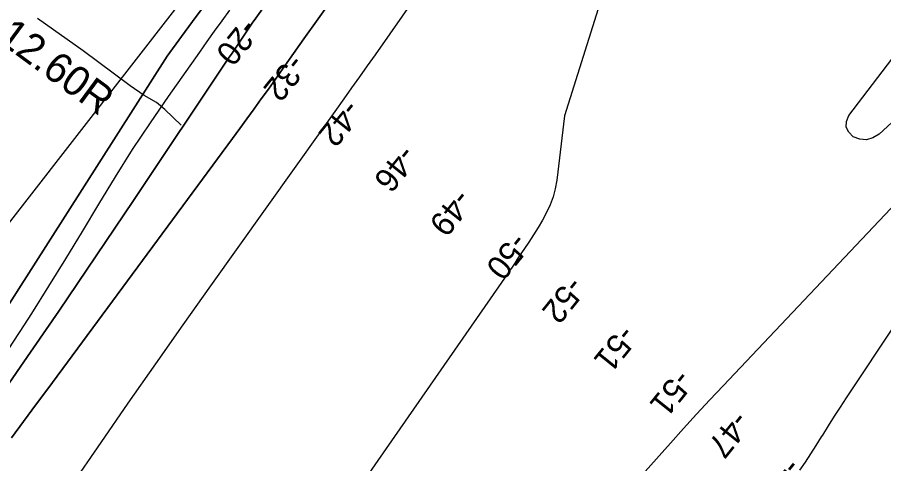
# Model space of a CAD drawing. Extents: x 3896831 to 3918110, y 171006 to 193349.
# Drawn here: x 3911133 to 3912353, y 185832 to 186461 of the extents above; entities that cross this region are included whole.
import ezdxf

# ---------------------------------------------------------------- set-up
doc = ezdxf.new("R2010")
doc.units = 0
for name, color, linetype in [('V-LEVE-TOET', 7, 'Continuous'), ('V-RIVR-RANG', 7, 'Continuous'), ('V-STRM-FMON', 7, 'Continuous'), ('V-TOPO-DPTH', 7, 'Continuous'), ('V-TOPO-MAJR', 7, 'Continuous'), ('V-TOPO-MINR', 7, 'Continuous')]:
    doc.layers.add(name, color=color, linetype=linetype)

msp = doc.modelspace()

# ---------------------------------------------------------------- linework, layer by layer
at = {"layer": 'V-LEVE-TOET'}
msp.add_lwpolyline([(3911363.8, 186309.1), (3911340.8, 186331.3), (3911329.3, 186341.2), (3911311.9, 186350.8), (3911292, 186364.5), (3911225.8, 186413.7), (3911161.8, 186459.6)], dxfattribs=at)
at = {"layer": 'V-TOPO-DPTH'}
for points in [[(3910975.3, 185824.5), (3910982.9, 185836.6), (3910990.4, 185848.6), (3910997.8, 185860.8), (3911005, 185873.1), (3911012, 185885.5), (3911344.1, 186406.2), (3911364.5, 186434.2), (3911384.9, 186462.3), (3911405.5, 186490.2), (3911426.2, 186518), (3911451, 186551), (3911484.1, 186595.3), (3911517.2, 186639.6), (3911550.2, 186683.9), (3911583.3, 186728.3), (3911836.5, 187068.6), (3911837.2, 187069.6), (3911839.4, 187072.5), (3911840.9, 187074.5), (3911842.4, 187076.4), (3912183.1, 187527.7)], [(3912020.4, 186958.3), (3911636.9, 186408.5), (3911626, 186392.9), (3911615, 186377.3), (3911604, 186361.8), (3911592.9, 186346.3), (3911580.3, 186328.6), (3911575.5, 186322), (3911570.8, 186315.3), (3911566, 186308.7), (3911561.3, 186302), (3911405.3, 186082.9), (3911366.4, 186027.9), (3911327.6, 185972.7), (3911289, 185917.3), (3911250.7, 185861.8), (3911208.3, 185800.1)], [(3912020.4, 186958.3), (3911636.9, 186408.5), (3911626, 186392.9), (3911615, 186377.3), (3911604, 186361.8), (3911592.9, 186346.3), (3911580.3, 186328.6), (3911575.5, 186322), (3911570.8, 186315.3), (3911566, 186308.7), (3911561.3, 186302), (3911405.3, 186082.9), (3911366.4, 186027.9), (3911327.6, 185972.7), (3911289, 185917.3), (3911250.7, 185861.8), (3911208.3, 185800.1)], [(3912235, 185822.9), (3912242.9, 185834.5), (3912250.7, 185846.2), (3912258.2, 185858), (3912265.7, 185869.9), (3912267.3, 185872.5), (3912275.5, 185885.7), (3912283.9, 185898.9), (3912292.3, 185911.9), (3912300.9, 185924.9), (3912442.8, 186138), (3912480.3, 186193), (3912518.5, 186247.6), (3912557.7, 186301.3), (3912597.7, 186354.6), (3912639.3, 186408.9), (3912659, 186434.6), (3912678.7, 186460.4), (3912698.3, 186486.2), (3912717.9, 186512), (3912941.8, 186807.2), (3912984.3, 186863.8), (3913012.1, 186901.3)], [(3912235, 185822.9), (3912242.9, 185834.5), (3912250.7, 185846.2), (3912258.2, 185858), (3912265.7, 185869.9), (3912267.3, 185872.5), (3912275.5, 185885.7), (3912283.9, 185898.9), (3912292.3, 185911.9), (3912300.9, 185924.9), (3912442.8, 186138), (3912480.3, 186193), (3912518.5, 186247.6), (3912557.7, 186301.3), (3912597.7, 186354.6), (3912639.3, 186408.9), (3912659, 186434.6), (3912678.7, 186460.4), (3912698.3, 186486.2), (3912717.9, 186512), (3912941.8, 186807.2), (3912984.3, 186863.8), (3913012.1, 186901.3)], [(3911757.1, 186865.4), (3911469, 186459.8), (3911464.1, 186452.8), (3911459.3, 186445.9), (3911454.5, 186438.9), (3911449.7, 186431.9), (3911445, 186424.8), (3911440.3, 186417.8), (3911435.5, 186410.8), (3911430.8, 186403.7), (3911296.8, 186203.2), (3911244.3, 186125.1), (3911191.5, 186047.2), (3911138.2, 185969.5), (3911084.7, 185892.1)], [(3911084.7, 185892.1), (3911138.2, 185969.5), (3911191.5, 186047.2), (3911244.3, 186125.1), (3911296.8, 186203.2), (3911430.8, 186403.7), (3911435.5, 186410.8), (3911440.3, 186417.8), (3911445, 186424.8), (3911449.7, 186431.9), (3911454.5, 186438.9), (3911459.3, 186445.9), (3911464.1, 186452.8), (3911469, 186459.8), (3911757.1, 186865.4)], [(3911577.1, 186487.5), (3911556.9, 186459.2), (3911536.8, 186430.9), (3911516.5, 186402.2), (3911506.6, 186388.1), (3911496.7, 186374.1), (3911486.7, 186360.1), (3911476.7, 186346.1), (3911466.6, 186332.1), (3911456.6, 186318.2), (3911446.4, 186304.3), (3911436.2, 186290.4), (3911182.5, 185946.8), (3911153.7, 185907.7), (3911125, 185868.6)], [(3911125, 185868.6), (3911153.7, 185907.7), (3911182.5, 185946.8), (3911436.2, 186290.4), (3911446.4, 186304.3), (3911456.6, 186318.2), (3911466.6, 186332.1), (3911476.7, 186346.1), (3911486.7, 186360.1), (3911496.7, 186374.1), (3911506.6, 186388.1), (3911516.5, 186402.2), (3911536.8, 186430.9), (3911556.9, 186459.2), (3911577.1, 186487.5)]]:
    msp.add_lwpolyline(points, dxfattribs=at)
at = {"layer": 'V-TOPO-MAJR'}
for points in [[(3912565, 186498.4), (3912346.6, 186296.5), (3912337.9, 186291.3), (3912328.9, 186288.6), (3912319.6, 186289.4), (3912310, 186292.7), (3912303.9, 186299.3), (3912300.4, 186306.5), (3912301, 186314.4), (3912304.2, 186322.8), (3912479.8, 186553.5)], [(3911956.1, 186489.8), (3911903.8, 186322.5), (3911892.9, 186231.5), (3911890.8, 186219.7), (3911887.9, 186208.1), (3911883.7, 186196.9), (3911878.6, 186186), (3911872.7, 186175.4), (3911866.7, 186165), (3911860.3, 186154.7), (3911853.7, 186144.5), (3911837.3, 186120.3), (3911833.6, 186114.8), (3911829.9, 186109.3), (3911826.1, 186103.8), (3911822.4, 186098.3), (3911641, 185836.6), (3911595.9, 185771.2)], [(3911712.5, 185480.3), (3912053, 185861.3), (3912071.4, 185881.7), (3912089.8, 185901.9), (3912108.5, 185922), (3912127.2, 185942), (3912420.2, 186251.8)]]:
    msp.add_lwpolyline(points, dxfattribs=at)
at = {"layer": 'V-TOPO-MINR'}
for points in [[(3912110.3, 187582.7), (3912109.9, 187582.2), (3912063, 187520.2), (3912016.3, 187458.1), (3911806, 187176.9), (3911786.7, 187150.5), (3911767.7, 187123.9), (3911749.1, 187097), (3911730.8, 187069.9), (3911675.8, 186986.6), (3911384.6, 186512.1), (3911369.5, 186491.3), (3911368.2, 186489.6), (3911365.6, 186486.1), (3911364.3, 186484.4), (3911362.3, 186481.8), (3911361, 186480), (3910921.7, 185915.3), (3910911.1, 185901.5), (3910900.5, 185887.7), (3910890, 185873.8), (3910879.6, 185859.8), (3910869.3, 185845.7), (3910859.2, 185831.5)], [(3912183.1, 187527.7), (3911842.4, 187076.4), (3911840.9, 187074.5), (3911839.4, 187072.5), (3911837.2, 187069.6), (3911836.5, 187068.6), (3911583.3, 186728.3), (3911550.2, 186683.9), (3911517.2, 186639.6), (3911484.1, 186595.3), (3911451, 186551), (3911426.2, 186518), (3911405.5, 186490.2), (3911384.9, 186462.3), (3911364.5, 186434.2), (3911344.1, 186406.2), (3911012, 185885.5), (3911005, 185873.1), (3910997.8, 185860.8), (3910990.4, 185848.6), (3910982.9, 185836.6), (3910975.3, 185824.5)], [(3912020.4, 186958.3), (3911636.9, 186408.5), (3911626, 186392.9), (3911615, 186377.3), (3911604, 186361.8), (3911592.9, 186346.3), (3911580.3, 186328.6), (3911575.5, 186322), (3911570.8, 186315.3), (3911566, 186308.7), (3911561.3, 186302), (3911405.3, 186082.9), (3911366.4, 186027.9), (3911327.6, 185972.7), (3911289, 185917.3), (3911250.7, 185861.8), (3911208.3, 185800.1)], [(3912235, 185822.9), (3912242.9, 185834.5), (3912250.7, 185846.2), (3912258.2, 185858), (3912265.7, 185869.9), (3912267.3, 185872.5), (3912275.5, 185885.7), (3912283.9, 185898.9), (3912292.3, 185911.9), (3912300.9, 185924.9), (3912442.8, 186138), (3912480.3, 186193), (3912518.5, 186247.6), (3912557.7, 186301.3), (3912597.7, 186354.6), (3912639.3, 186408.9), (3912659, 186434.6), (3912678.7, 186460.4), (3912698.3, 186486.2), (3912717.9, 186512), (3912941.8, 186807.2), (3912984.3, 186863.8), (3913012.1, 186901.3)], [(3911757.1, 186865.4), (3911469, 186459.8), (3911464.1, 186452.8), (3911459.3, 186445.9), (3911454.5, 186438.9), (3911449.7, 186431.9), (3911445, 186424.8), (3911440.3, 186417.8), (3911435.5, 186410.8), (3911430.8, 186403.7), (3911296.8, 186203.2), (3911244.3, 186125.1), (3911191.5, 186047.2), (3911138.2, 185969.5), (3911084.7, 185892.1)], [(3911577.1, 186487.5), (3911556.9, 186459.2), (3911536.8, 186430.9), (3911516.5, 186402.2), (3911506.6, 186388.1), (3911496.7, 186374.1), (3911486.7, 186360.1), (3911476.7, 186346.1), (3911466.6, 186332.1), (3911456.6, 186318.2), (3911446.4, 186304.3), (3911436.2, 186290.4), (3911182.5, 185946.8), (3911153.7, 185907.7), (3911125, 185868.6)], [(3911431.8, 186471.1), (3911421.2, 186456.4), (3911410.5, 186441.7), (3911400, 186426.9), (3911389.5, 186412), (3911345.6, 186349.7), (3911320.1, 186312.5), (3911295.1, 186274.8), (3911271.1, 186236.6), (3911247.6, 186198), (3911224.4, 186159.2), (3911200.9, 186120.6), (3911177.1, 186082.2), (3911153, 186044), (3911142.6, 186027.8), (3911112.9, 185981.7)]]:
    msp.add_lwpolyline(points, dxfattribs=at)

# ---------------------------------------------------------------- texts
at = {"layer": 'V-RIVR-RANG'}
for s, rotation, p in [('-20', 231.0783, (3911451.6, 186461.5)), ('-32', 231.2165, (3911518.4, 186411.1)), ('-42', 231.2165, (3911595.9, 186347.2)), ('-46', 231.2165, (3911674.2, 186283.2)), ('-49', 231.2165, (3911752.1, 186221.1)), ('-50', 231.2165, (3911831.9, 186159.7)), ('-52', 231.2165, (3911910.8, 186098.1)), ('-51', 231.2165, (3911983.8, 186029.5)), ('-51', 231.2165, (3912062.5, 185966.9)), ('-47', 231.2165, (3912143.6, 185908.6)), ('-41', 231.2165, (3912217.9, 185841.9))]:
    msp.add_text(s, height=33.5, rotation=rotation, dxfattribs=at).set_placement(p)
at = {"layer": 'V-STRM-FMON'}
msp.add_text('12.60R', height=42, rotation=323.6306, dxfattribs=at).set_placement((3911103.2, 186428.8))

doc.saveas('drawing.dxf')
